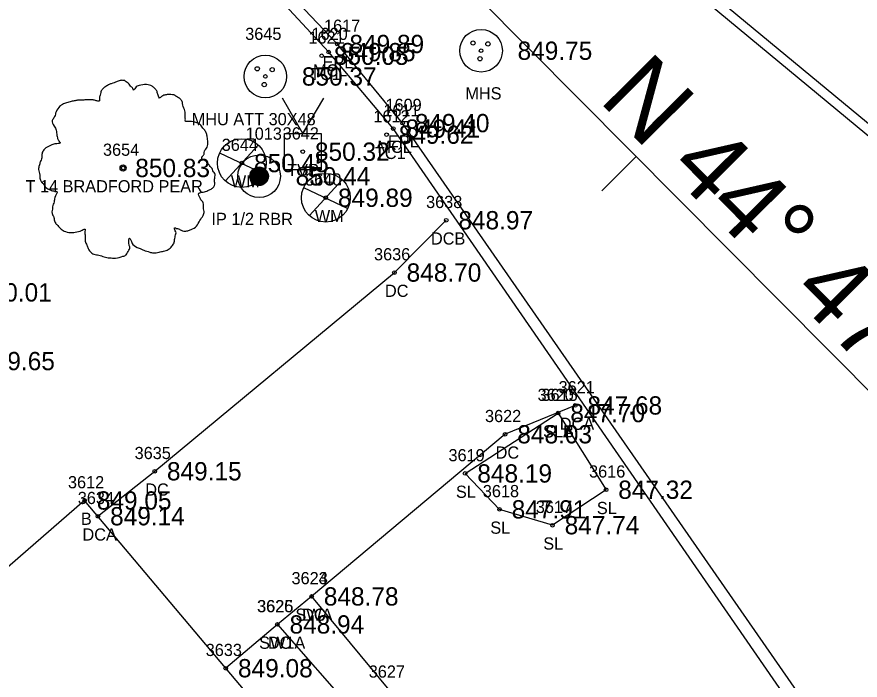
# Model space of a CAD drawing. Extents: x 1622501 to 1626664, y 1117816 to 1121579.
# Drawn here: x 1624749.2 to 1624818.4, y 1120113.7 to 1120168.1 of the extents above; entities that cross this region are included whole.
import ezdxf

# ---------------------------------------------------------------- set-up
doc = ezdxf.new("R2010")
doc.units = 0
for name, color, linetype in [('RD_EX_Bldg', 7, 'Continuous'), ('RD_EX_Bldg_txCode', 7, 'Continuous'), ('RD_EX_Conc', 7, 'Continuous'), ('RD_EX_Conc_txCode', 7, 'Continuous'), ('RD_EX_DR_Inlet', 7, 'Continuous'), ('RD_EX_DV_Prop_txCode', 7, 'Continuous'), ('RD_EX_DV_PropPin', 7, 'Continuous'), ('RD_EX_Road', 7, 'Continuous'), ('RD_EX_Road_txCode', 7, 'Continuous'), ('RD_EX_TX_Bldg_ELEV', 7, 'Continuous'), ('RD_EX_TX_Conc_ELEV', 7, 'Continuous'), ('RD_EX_TX_DV_Prop_ELEV', 7, 'Continuous'), ('RD_EX_TX_Road_ELEV', 7, 'Continuous'), ('RD_EX_TX_UT_ELEV', 7, 'Continuous'), ('RD_EX_TX_VEG_ELEV', 7, 'Continuous'), ('RD_EX_UT', 7, 'Continuous'), ('RD_EX_UT_txCode', 7, 'Continuous'), ('RD_EX_VEG', 7, 'Continuous'), ('RD_EX_VEG_txCode', 7, 'Continuous'), ('RD_HC_Cl', 7, 'Continuous'), ('RD_HC_Data', 7, 'Continuous'), ('RD_HC_Data_Tic', 7, 'Continuous'), ('RD_SMD_Locator', 7, 'Continuous')]:
    doc.layers.add(name, color=color, linetype=linetype)

msp = doc.modelspace()

# ---------------------------------------------------------------- linework, layer by layer
at = {"layer": 'RD_EX_Bldg'}
msp.add_lwpolyline([(1624761.471, 1120072.269), (1624784.901, 1120092.591), (1624754.727, 1120128.417), (1624731.297, 1120108.095), (1624761.471, 1120072.269)], dxfattribs=at)
at = {"layer": 'RD_EX_Conc'}
for points in [[(1624782.174, 1120199.047), (1624784.892, 1120189.449), (1624788.803, 1120184.422), (1624820.359, 1120158.326), (1624851.407, 1120132.805)], [(1624817.068, 1120105.388), (1624780.068, 1120158.943), (1624774.769, 1120165.218), (1624757.385, 1120183.939)], [(1624755.816, 1120127.124), (1624760.485, 1120130.815), (1624780.172, 1120147.128), (1624784.422, 1120151.421)], [(1624795.021, 1120136.217), (1624789.261, 1120133.852), (1624773.371, 1120120.542), (1624770.555, 1120118.243), (1624766.322, 1120114.65)], [(1624773.371, 1120120.542), (1624779.714, 1120112.874), (1624781.452, 1120107.42), (1624777.462, 1120101.588)], [(1624770.555, 1120118.243), (1624776.948, 1120110.956), (1624777.791, 1120107.139), (1624775.004, 1120104.519)]]:
    msp.add_lwpolyline(points, dxfattribs=at)
at = {"layer": 'RD_EX_DR_Inlet'}
for centre, radius in [((1624787.285, 1120165.336), 1.75), ((1624786.621, 1120165.966), 0.175), ((1624787.845, 1120165.896), 0.175), ((1624769.569, 1120163.219), 1.75), ((1624787.198, 1120164.672), 0.175), ((1624768.904, 1120163.849), 0.175), ((1624770.129, 1120163.779), 0.175), ((1624769.481, 1120162.554), 0.175)]:
    msp.add_circle(centre, radius, dxfattribs=at)
at = {"layer": 'RD_EX_DV_PropPin'}
for p, q in [((1624768.46, 1120154.555), (1624768.46, 1120155.504)), ((1624768.495, 1120154.514), (1624768.495, 1120155.544)), ((1624768.53, 1120154.479), (1624768.53, 1120155.58)), ((1624768.565, 1120154.447), (1624768.565, 1120155.612)), ((1624768.6, 1120154.42), (1624768.6, 1120155.639)), ((1624768.635, 1120154.395), (1624768.635, 1120155.664)), ((1624768.67, 1120154.373), (1624768.67, 1120155.686)), ((1624768.705, 1120154.354), (1624768.705, 1120155.705)), ((1624768.74, 1120154.337), (1624768.74, 1120155.722)), ((1624768.775, 1120154.322), (1624768.775, 1120155.737)), ((1624768.81, 1120154.309), (1624768.81, 1120155.75)), ((1624768.845, 1120154.298), (1624768.845, 1120155.761)), ((1624768.88, 1120154.289), (1624768.88, 1120155.77)), ((1624768.915, 1120154.281), (1624768.915, 1120155.777)), ((1624768.95, 1120154.276), (1624768.95, 1120155.783)), ((1624768.985, 1120154.272), (1624768.985, 1120155.787)), ((1624769.02, 1120154.269), (1624769.02, 1120155.79)), ((1624769.055, 1120154.268), (1624769.055, 1120155.79)), ((1624769.09, 1120154.269), (1624769.09, 1120155.79)), ((1624769.126, 1120154.272), (1624769.126, 1120155.787)), ((1624769.161, 1120154.276), (1624769.161, 1120155.783)), ((1624769.196, 1120154.281), (1624769.196, 1120155.777)), ((1624769.231, 1120154.289), (1624769.231, 1120155.77)), ((1624769.266, 1120154.298), (1624769.266, 1120155.761)), ((1624769.301, 1120154.309), (1624769.301, 1120155.75)), ((1624769.336, 1120154.322), (1624769.336, 1120155.737)), ((1624769.371, 1120154.337), (1624769.371, 1120155.722)), ((1624769.406, 1120154.354), (1624769.406, 1120155.705)), ((1624769.441, 1120154.373), (1624769.441, 1120155.686)), ((1624769.476, 1120154.395), (1624769.476, 1120155.664)), ((1624769.511, 1120154.42), (1624769.511, 1120155.639)), ((1624769.546, 1120154.447), (1624769.546, 1120155.612)), ((1624769.581, 1120154.479), (1624769.581, 1120155.58)), ((1624769.616, 1120154.514), (1624769.616, 1120155.544)), ((1624769.651, 1120154.555), (1624769.651, 1120155.504)), ((1624768.32, 1120154.833), (1624768.32, 1120155.226)), ((1624768.355, 1120154.731), (1624768.355, 1120155.327)), ((1624768.39, 1120154.66), (1624768.39, 1120155.399)), ((1624768.425, 1120154.603), (1624768.425, 1120155.456)), ((1624769.686, 1120154.603), (1624769.686, 1120155.456)), ((1624769.721, 1120154.66), (1624769.721, 1120155.399)), ((1624769.756, 1120154.731), (1624769.756, 1120155.327)), ((1624769.791, 1120154.833), (1624769.791, 1120155.226))]:
    msp.add_line(p, q, dxfattribs=at)
for radius in [1.75, 0.761]:
    msp.add_circle((1624769.055, 1120155.029), radius, dxfattribs=at)
at = {"layer": 'RD_EX_Road'}
for points in [[(1624781.367, 1120199.017), (1624784.165, 1120188.994), (1624788.317, 1120183.838), (1624819.769, 1120157.812), (1624850.784, 1120132.057), (1624863.119, 1120123.17), (1624872.562, 1120120.776), (1624881.482, 1120120.158), (1624884.455, 1120120.692), (1624898.026, 1120126.784), (1624903.404, 1120131.449), (1624903.183, 1120131.678), (1624904.185, 1120132.725), (1624940.396, 1120166.874), (1624977.651, 1120202.124), (1625014.07, 1120236.514), (1625050.075, 1120270.322), (1625084.777, 1120302.734), (1625122.295, 1120338.035), (1625158.189, 1120371.975), (1625193.609, 1120405.268), (1625230.886, 1120440.454)], [(1624468.776, 1119721.97), (1624504.417, 1119755.418), (1624540.918, 1119789.518), (1624577.003, 1119823.632), (1624614.114, 1119858.363), (1624622.032, 1119866.661), (1624623.941, 1119868.415), (1624624.904, 1119868.053), (1624628.911, 1119871.896), (1624628.355, 1119872.684), (1624649.217, 1119892.427), (1624685.623, 1119926.575), (1624722.144, 1119961.012), (1624758.273, 1119995.003), (1624794.851, 1120029.549), (1624818.75, 1120051.929), (1624828.768, 1120068.769), (1624829.584, 1120080.906), (1624828.334, 1120088.311), (1624824.847, 1120095.343), (1624817.994, 1120105.913), (1624780.843, 1120159.392), (1624775.475, 1120165.887), (1624755.046, 1120187.376)]]:
    msp.add_lwpolyline(points, dxfattribs=at)
at = {"layer": 'RD_EX_UT'}
for p, q in [((1624772.643, 1120158.549), (1624770.976, 1120161.435)), ((1624772.643, 1120158.549), (1624774.383, 1120161.435)), ((1624766.286, 1120154.655), (1624768.954, 1120157.551)), ((1624765.805, 1120156.95), (1624769.436, 1120155.237)), ((1624772.701, 1120154.102), (1624776.332, 1120152.389)), ((1624773.183, 1120151.806), (1624775.85, 1120154.703))]:
    msp.add_line(p, q, dxfattribs=at)
msp.add_lwpolyline([(1624771.143, 1120155.549), (1624771.143, 1120158.549), (1624774.143, 1120158.549), (1624774.143, 1120155.549)], close=True, dxfattribs=at)
for centre in [(1624767.639, 1120156.113), (1624774.535, 1120153.264)]:
    msp.add_circle(centre, 2, dxfattribs=at)
at = {"layer": 'RD_EX_VEG'}
msp.add_lwpolyline([(1624793.618, 1120135.589), (1624797.55, 1120129.3), (1624793.152, 1120126.388), (1624788.8, 1120127.688), (1624785.979, 1120130.634), (1624793.618, 1120135.589)], dxfattribs=at)
for centre, radius in [((1624757.887, 1120155.71), 0.25), ((1624757.874, 1120155.691), 0.0001)]:
    msp.add_circle(centre, radius, dxfattribs=at)
for points in [[(1624758.019, 1120162.877), (1624757.719, 1120162.902), (1624757.394, 1120162.802), (1624757.144, 1120162.702), (1624756.919, 1120162.627), (1624756.694, 1120162.527), (1624756.395, 1120162.353), (1624756.17, 1120162.153), (1624756.045, 1120161.903), (1624755.995, 1120161.678), (1624755.945, 1120161.403), (1624755.945, 1120161.228), (1624755.82, 1120161.203), (1624755.67, 1120161.228), (1624755.42, 1120161.303), (1624755.17, 1120161.303), (1624754.92, 1120161.303), (1624754.57, 1120161.278), (1624754.22, 1120161.278), (1624753.946, 1120161.228), (1624753.621, 1120161.178), (1624753.246, 1120161.053), (1624752.896, 1120160.928), (1624752.596, 1120160.678), (1624752.346, 1120160.203), (1624752.221, 1120159.854), (1624752.071, 1120159.604), (1624752.221, 1120159.154), (1624752.396, 1120158.804), (1624752.421, 1120158.604), (1624752.496, 1120158.179), (1624752.596, 1120157.954), (1624752.721, 1120157.754), (1624752.646, 1120157.73), (1624752.271, 1120157.68), (1624751.971, 1120157.58), (1624751.547, 1120157.355), (1624751.322, 1120157.13), (1624751.222, 1120156.805), (1624751.197, 1120156.455), (1624751.097, 1120156.255), (1624751.022, 1120155.98), (1624750.997, 1120155.905), (1624750.947, 1120155.58), (1624751.047, 1120155.131), (1624751.072, 1120154.781), (1624751.197, 1120154.556), (1624751.347, 1120154.381), (1624751.522, 1120154.131), (1624751.921, 1120153.906), (1624752.246, 1120153.806), (1624752.446, 1120153.781), (1624752.271, 1120153.281), (1624752.221, 1120152.932), (1624752.096, 1120152.532), (1624752.096, 1120152.457), (1624752.046, 1120151.982), (1624752.196, 1120151.657), (1624752.271, 1120151.282), (1624752.446, 1120151.057), (1624752.721, 1120150.758), (1624753.046, 1120150.533), (1624753.546, 1120150.408), (1624753.946, 1120150.433), (1624754.52, 1120150.608), (1624754.77, 1120150.683), (1624754.745, 1120150.508), (1624754.77, 1120150.133), (1624754.77, 1120149.708), (1624754.92, 1120149.383), (1624755.02, 1120149.108), (1624755.17, 1120148.858), (1624755.495, 1120148.634), (1624755.895, 1120148.559), (1624756.32, 1120148.409), (1624756.769, 1120148.334), (1624757.269, 1120148.309), (1624757.869, 1120148.459), (1624758.144, 1120148.584), (1624758.244, 1120148.758), (1624758.444, 1120149.133), (1624758.394, 1120149.358), (1624758.419, 1120149.958), (1624758.519, 1120149.783), (1624758.694, 1120149.433), (1624759.193, 1120149.133), (1624759.593, 1120148.958), (1624760.068, 1120148.808), (1624760.368, 1120148.733), (1624760.843, 1120148.808), (1624761.217, 1120148.883), (1624761.592, 1120149.008), (1624761.892, 1120149.283), (1624762.067, 1120149.558), (1624762.117, 1120149.833), (1624762.192, 1120150.208), (1624762.242, 1120150.383)], [(1624762.242, 1120150.383), (1624762.167, 1120150.558), (1624762.117, 1120150.808), (1624762.192, 1120150.783), (1624762.367, 1120150.733), (1624762.642, 1120150.608), (1624762.867, 1120150.533), (1624763.192, 1120150.558), (1624763.466, 1120150.658), (1624763.916, 1120150.933), (1624764.191, 1120151.407), (1624764.466, 1120151.807), (1624764.541, 1120152.132), (1624764.491, 1120152.357), (1624764.466, 1120152.857), (1624764.266, 1120153.107), (1624764.216, 1120153.231), (1624764.116, 1120153.631), (1624764.191, 1120153.681), (1624764.466, 1120153.731), (1624764.841, 1120153.856), (1624765.116, 1120153.981), (1624765.341, 1120154.156), (1624765.416, 1120154.381), (1624765.391, 1120154.781), (1624765.441, 1120155.181), (1624765.366, 1120155.331), (1624765.266, 1120155.48), (1624765.191, 1120155.68), (1624765.041, 1120155.83), (1624764.941, 1120155.98), (1624764.841, 1120156.08), (1624764.716, 1120156.23), (1624764.541, 1120156.355), (1624764.391, 1120156.405), (1624764.341, 1120156.555), (1624764.491, 1120156.755), (1624764.541, 1120156.855), (1624764.566, 1120157.08), (1624764.791, 1120157.43), (1624764.841, 1120157.829), (1624764.791, 1120158.254), (1624764.741, 1120158.529), (1624764.591, 1120158.804), (1624764.391, 1120159.054), (1624764.266, 1120159.229), (1624764.091, 1120159.354), (1624763.766, 1120159.479), (1624763.516, 1120159.529), (1624763.167, 1120159.529), (1624762.967, 1120159.579), (1624762.992, 1120159.629), (1624762.992, 1120159.779), (1624762.992, 1120160.054), (1624762.917, 1120160.503), (1624762.767, 1120161.003), (1624762.767, 1120161.028), (1624762.667, 1120161.278), (1624762.442, 1120161.478), (1624762.267, 1120161.578), (1624762.067, 1120161.703), (1624761.817, 1120161.728), (1624761.517, 1120161.728), (1624761.242, 1120161.678), (1624761.042, 1120161.578), (1624760.868, 1120161.453), (1624760.793, 1120161.603), (1624760.693, 1120161.903), (1624760.643, 1120162.053), (1624760.493, 1120162.228), (1624760.268, 1120162.427), (1624759.818, 1120162.552), (1624759.193, 1120162.477), (1624758.893, 1120162.278), (1624758.743, 1120162.103), (1624758.694, 1120162.228), (1624758.494, 1120162.427), (1624758.394, 1120162.602), (1624758.219, 1120162.727), (1624758.069, 1120162.827), (1624757.969, 1120162.877)]]:
    msp.add_spline(points, degree=3, dxfattribs=at)
at = {"layer": 'RD_HC_Cl'}
msp.add_line((1624870.491, 1120085.684), (1624760.808, 1120196.145), dxfattribs=at)
at = {"layer": 'RD_HC_Data_Tic'}
msp.add_line((1624800.031, 1120156.644), (1624797.192, 1120153.825), dxfattribs=at)
at = {"layer": 'RD_SMD_Locator'}
for centre in [(1624775.475, 1120165.887), (1624774.769, 1120165.218), (1624787.285, 1120165.336), (1624774.196, 1120164.922), (1624769.569, 1120163.219), (1624780.068, 1120158.943), (1624780.843, 1120159.392), (1624779.527, 1120158.444), (1624772.643, 1120157.049), (1624767.639, 1120156.113), (1624757.887, 1120155.71), (1624769.056, 1120155.029), (1624774.535, 1120153.264), (1624784.422, 1120151.421), (1624780.172, 1120147.128), (1624795.021, 1120136.217), (1624793.618, 1120135.589), (1624793.618, 1120135.589), (1624789.261, 1120133.852), (1624760.485, 1120130.815), (1624785.979, 1120130.634), (1624797.55, 1120129.3), (1624754.727, 1120128.417), (1624788.8, 1120127.688), (1624755.816, 1120127.124), (1624793.152, 1120126.388), (1624773.371, 1120120.542), (1624773.371, 1120120.542), (1624770.555, 1120118.243), (1624770.555, 1120118.243), (1624766.322, 1120114.65)]:
    msp.add_circle(centre, 0.15, dxfattribs=at)

# ---------------------------------------------------------------- texts
at = {"layer": 'RD_EX_Bldg_txCode'}
for s, p in [('3612', (1624753.357, 1120129.417)), ('B', (1624754.42, 1120126.417))]:
    msp.add_text(s, height=1, dxfattribs=at).set_placement(p)
at = {"layer": 'RD_EX_Conc_txCode'}
for s, p in [('1621', (1624773.109, 1120165.922)), ('1620', (1624773.36, 1120166.218)), ('TC1', (1624773.235, 1120162.922)), ('MCL', (1624773.478, 1120163.218)), ('1612', (1624778.44, 1120159.444)), ('1611', (1624779.264, 1120159.943)), ('MCL', (1624778.776, 1120156.943)), ('TC1', (1624778.566, 1120156.444)), ('3638', (1624782.769, 1120152.421)), ('DCB', (1624783.17, 1120149.421)), ('3636', (1624778.495, 1120148.128)), ('DC', (1624779.392, 1120145.128)), ('3621', (1624793.651, 1120137.217)), ('3622', (1624787.608, 1120134.852)), ('DCA', (1624793.753, 1120134.217)), ('3635', (1624758.831, 1120131.815)), ('DC', (1624788.482, 1120131.852)), ('DC', (1624759.705, 1120128.815)), ('3634', (1624754.163, 1120128.124)), ('DCA', (1624754.548, 1120125.124)), ('3623', (1624771.718, 1120121.542)), ('3624', (1624771.718, 1120121.542)), ('3626', (1624768.878, 1120119.243)), ('3625', (1624768.901, 1120119.243)), ('SWA', (1624772.04, 1120118.542)), ('DC', (1624772.592, 1120118.542)), ('SW1A', (1624769.059, 1120116.243)), ('DC', (1624769.775, 1120116.243)), ('3633', (1624764.669, 1120115.65)), ('3627', (1624778.06, 1120113.874))]:
    msp.add_text(s, height=1, dxfattribs=at).set_placement(p)
at = {"layer": 'RD_EX_DV_Prop_txCode'}
for s, p in [('1013', (1624767.953, 1120158.029)), ('IP 1/2 RBR', (1624765.142, 1120151.029))]:
    msp.add_text(s, height=1, dxfattribs=at).set_placement(p)
at = {"layer": 'RD_EX_Road_txCode'}
for s, p in [('1617', (1624774.388, 1120166.887)), ('EPL', (1624774.27, 1120163.887)), ('1609', (1624779.433, 1120160.392)), ('EPL', (1624779.638, 1120157.392))]:
    msp.add_text(s, height=1, dxfattribs=at).set_placement(p)
at = {"layer": 'RD_EX_TX_Bldg_ELEV'}
for s, p in [('850.01', (1624745.889, 1120144.748)), ('849.05', (1624755.727, 1120127.667))]:
    msp.add_text(s, height=1.5, dxfattribs=at).set_placement(p)
at = {"layer": 'RD_EX_TX_Conc_ELEV'}
for s, p in [('849.85', (1624775.769, 1120164.468)), ('850.05', (1624775.196, 1120164.172)), ('849.41', (1624781.068, 1120158.193)), ('849.62', (1624780.527, 1120157.694)), ('848.97', (1624785.422, 1120150.671)), ('848.70', (1624781.172, 1120146.378)), ('847.68', (1624796.021, 1120135.467)), ('848.03', (1624790.261, 1120133.102)), ('849.15', (1624761.485, 1120130.065)), ('849.14', (1624756.816, 1120126.374)), ('848.78', (1624774.371, 1120119.792)), ('848.78', (1624774.371, 1120119.792)), ('848.94', (1624771.555, 1120117.493)), ('848.94', (1624771.555, 1120117.493)), ('849.08', (1624767.322, 1120113.9))]:
    msp.add_text(s, height=1.5, dxfattribs=at).set_placement(p)
at = {"layer": 'RD_EX_TX_DV_Prop_ELEV'}
msp.add_text('850.44', height=1.5, dxfattribs=at).set_placement((1624772.056, 1120154.279))
at = {"layer": 'RD_EX_TX_Road_ELEV'}
for s, p in [('849.89', (1624776.475, 1120165.137)), ('849.40', (1624781.843, 1120158.642))]:
    msp.add_text(s, height=1.5, dxfattribs=at).set_placement(p)
at = {"layer": 'RD_EX_TX_UT_ELEV'}
for s, p in [('849.75', (1624790.285, 1120164.586)), ('850.37', (1624772.569, 1120162.469)), ('850.32', (1624773.643, 1120156.299)), ('850.45', (1624768.639, 1120155.363)), ('849.89', (1624775.535, 1120152.514))]:
    msp.add_text(s, height=1.5, dxfattribs=at).set_placement(p)
at = {"layer": 'RD_EX_TX_VEG_ELEV'}
for s, p in [('850.83', (1624758.887, 1120154.96)), ('849.65', (1624746.146, 1120139.111)), ('847.70', (1624794.618, 1120134.839)), ('847.70', (1624794.618, 1120134.839)), ('848.19', (1624786.979, 1120129.884)), ('847.32', (1624798.55, 1120128.55)), ('847.91', (1624789.8, 1120126.938)), ('847.74', (1624794.152, 1120125.638))]:
    msp.add_text(s, height=1.5, dxfattribs=at).set_placement(p)
at = {"layer": 'RD_EX_UT_txCode'}
for s, p in [('3645', (1624767.915, 1120166.219)), ('MHS', (1624785.994, 1120161.336)), ('MHU ATT 30X48', (1624763.522, 1120159.219)), ('3642', (1624770.989, 1120158.049)), ('3644', (1624765.985, 1120157.113)), ('TVP', (1624771.359, 1120155.049)), ('WM', (1624766.733, 1120154.113)), ('3640', (1624772.842, 1120154.264)), ('WM', (1624773.629, 1120151.264))]:
    msp.add_text(s, height=1, dxfattribs=at).set_placement(p)
at = {"layer": 'RD_EX_VEG_txCode'}
for s, p in [('3654', (1624756.233, 1120156.71)), ('T 14 BRADFORD PEAR', (1624749.871, 1120153.71)), ('3620', (1624791.925, 1120136.589)), ('3615', (1624792.248, 1120136.589)), ('SLA', (1624792.374, 1120133.589)), ('SLB', (1624792.39, 1120133.589)), ('3619', (1624784.609, 1120131.634)), ('3616', (1624796.156, 1120130.3)), ('SL', (1624785.223, 1120128.634)), ('3618', (1624787.43, 1120128.688)), ('3617', (1624791.782, 1120127.388)), ('SL', (1624796.794, 1120127.3)), ('SL', (1624788.044, 1120125.688)), ('SL', (1624792.396, 1120124.388))]:
    msp.add_text(s, height=1, dxfattribs=at).set_placement(p)
at = {"layer": 'RD_HC_Data'}
msp.add_text('N 44%%d 47\' 51" W', height=6, rotation=314.79754, dxfattribs=at).set_placement((1624796.869, 1120161.247))

doc.saveas('drawing.dxf')
